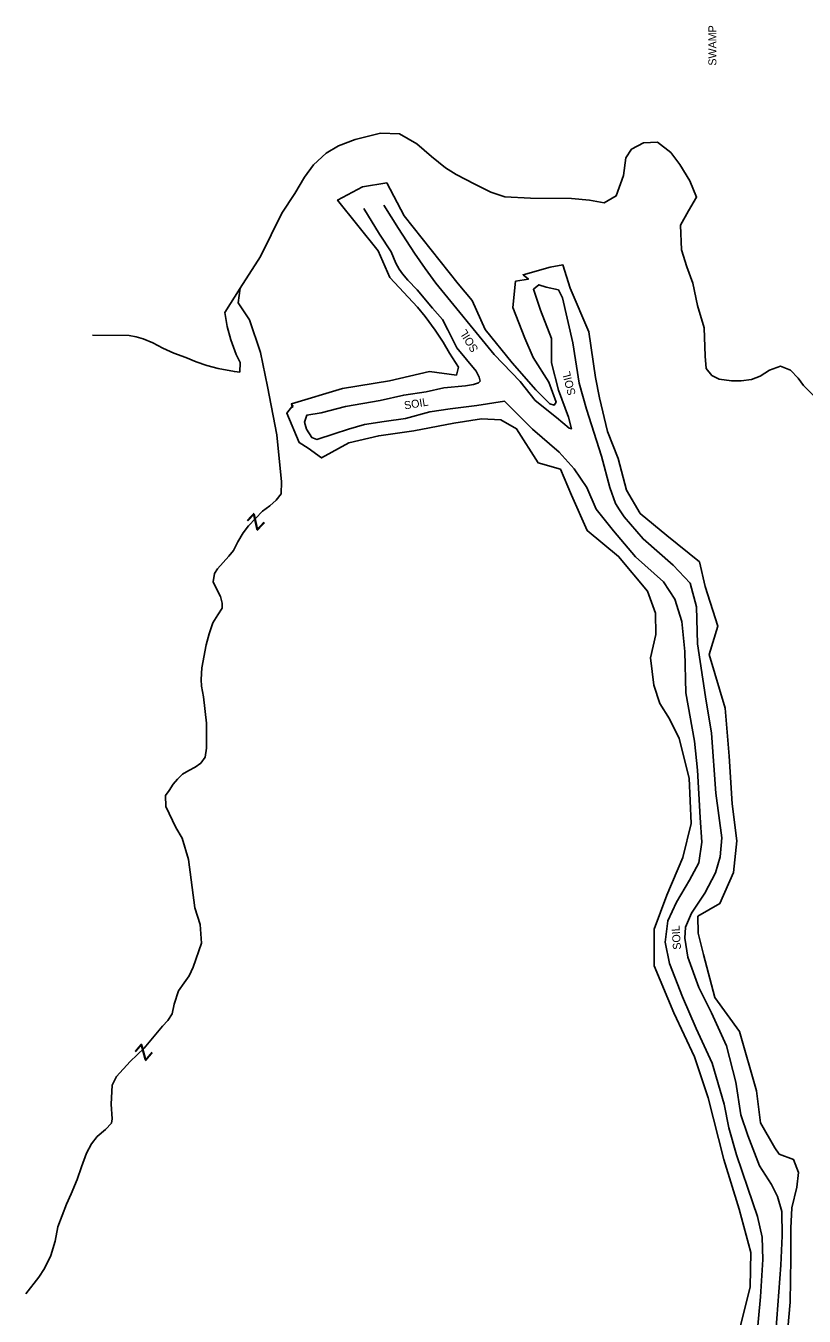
# Model space of a CAD drawing. Extents: x 2030130 to 2036320, y 723205 to 762423.
# Drawn here: x 2031445 to 2031834, y 751056 to 751701 of the extents above; entities that cross this region are included whole.
import ezdxf

# ---------------------------------------------------------------- set-up
doc = ezdxf.new("R2010")
doc.units = 0
for name, color, linetype in [('Draft_Station Labels Major', 7, 'Continuous'), ('Draft_Station Tics Major', 7, 'Continuous'), ('Old_Level_23', 7, 'Continuous'), ('Prop Alignment Horizontal', 7, 'Continuous'), ('Prop Alignment Vertical', 7, 'Continuous')]:
    doc.layers.add(name, color=color, linetype=linetype)

msp = doc.modelspace()

# ---------------------------------------------------------------- linework, layer by layer
at = {"layer": 'Draft_Station Labels Major'}
for points in [[(2031613.92, 751610.21), (2031621.77, 751597.41), (2031627.56, 751588.5), (2031629.94, 751582.79), (2031631.52, 751579.85), (2031633.27, 751577.58), (2031635.91, 751574.36), (2031640.58, 751569.46)], [(2031623.85, 751611.89), (2031631.21, 751600.23), (2031639.15, 751587.81), (2031644.53, 751580.24), (2031649.81, 751572.85)], [(2031810.37, 751046.17), (2031812.15, 751066.06), (2031813.37, 751084.7), (2031813.04, 751095.89), (2031810.7, 751106.18), (2031805.8, 751120.4), (2031800.09, 751137.02), (2031796.26, 751150.48), (2031793.99, 751162.32), (2031788.05, 751182.89), (2031780.02, 751200.16), (2031773.17, 751216), (2031766.6, 751232.7), (2031764.54, 751243.39), (2031765.86, 751254.11), (2031770.09, 751263.33), (2031776.61, 751274.41), (2031781.32, 751283.05), (2031782.74, 751293.39), (2031782.01, 751305.73), (2031780.57, 751329.35), (2031779.13, 751343.9), (2031774.79, 751368.07), (2031774.24, 751388.71), (2031772.8, 751403.74), (2031769.39, 751414.89), (2031763.69, 751423.5), (2031749.74, 751435.97), (2031738.68, 751448.96), (2031729.96, 751459.85), (2031725.29, 751470.6), (2031719, 751479.98), (2031711.57, 751488.28), (2031698.21, 751499.89), (2031684.24, 751513.8), (2031670.28, 751511.7), (2031657.08, 751510), (2031646.87, 751508.52), (2031634.76, 751505.19), (2031623.97, 751503.61), (2031614.15, 751502.23), (2031606.26, 751499.82), (2031598.96, 751497.51), (2031590.31, 751494.71), (2031587.79, 751495.74), (2031585.23, 751499.85), (2031584.22, 751503.31), (2031585.43, 751506.9), (2031592.46, 751508.05), (2031604.68, 751511.19), (2031622.01, 751514.2), (2031633.84, 751516.85), (2031645.01, 751518.53), (2031653.86, 751520.47), (2031664.66, 751521.47), (2031668.61, 751522.1), (2031671.2, 751523), (2031671.96, 751523.88), (2031671.55, 751525.8), (2031669.97, 751528.77), (2031660.37, 751540.52), (2031655.92, 751549.44), (2031653.25, 751554.62), (2031648.26, 751560.35), (2031640.58, 751569.46)], [(2031649.81, 751572.85), (2031679.08, 751537.1), (2031692.07, 751523.75), (2031699.52, 751514.1), (2031710.14, 751505.74), (2031716.48, 751500.32), (2031717.74, 751500.04), (2031716.22, 751505.81), (2031711.23, 751519.26), (2031707.68, 751533.01), (2031707.71, 751539.19), (2031707.73, 751545.17), (2031702.15, 751559.28), (2031698.65, 751569.76), (2031701.42, 751572.01), (2031705, 751570.9), (2031711.1, 751569.52), (2031713.17, 751565.5), (2031718.27, 751542.98), (2031721.51, 751522.86), (2031725.14, 751509.88), (2031732.66, 751486.33), (2031736.91, 751470.76), (2031739.71, 751462.69), (2031741.58, 751459.52), (2031743.94, 751456.08), (2031753.43, 751445), (2031768.45, 751431.87), (2031777.05, 751422.81), (2031780.09, 751411.08), (2031780.61, 751392.47), (2031784.59, 751366.08), (2031787.62, 751347.79), (2031789.82, 751317.9), (2031792.79, 751295.56), (2031792.04, 751286), (2031789.63, 751278.06), (2031784.35, 751267.86), (2031777.62, 751257.94), (2031774.62, 751250.95), (2031774.3, 751245.36), (2031775.86, 751235.92), (2031781.26, 751220.65), (2031787.59, 751208.08), (2031795.22, 751191.49), (2031799.79, 751173.31), (2031802.3, 751157.13), (2031805.8, 751146.66), (2031811.68, 751131.48), (2031817.68, 751122.3), (2031820.65, 751116.25), (2031822.77, 751108.76), (2031822.92, 751096.5), (2031822.23, 751081.93), (2031818.25, 751028.53)]]:
    msp.add_lwpolyline(points, dxfattribs=at)
at = {"layer": 'Draft_Station Tics Major'}
for points in [[(2031660.95, 751572.51), (2031633.97, 751606.5), (2031625.29, 751622.94), (2031613.23, 751621.03), (2031600.71, 751614.37), (2031621.03, 751589.02), (2031626.87, 751575.72), (2031640.68, 751560.79)], [(2031825.28, 751044.6), (2031827.02, 751063.4), (2031827.26, 751085.45), (2031827.34, 751100.35), (2031827.87, 751110.54), (2031830.31, 751120.81), (2031831.14, 751128.17), (2031828.63, 751134.78), (2031821.5, 751137.38), (2031819.24, 751140.53), (2031812.19, 751153.05), (2031810.13, 751169.1), (2031801.63, 751198.74), (2031789.29, 751215.65), (2031783.58, 751237.26), (2031781.02, 751247.86), (2031780.85, 751256.32), (2031791.82, 751262.65), (2031798.65, 751278.17), (2031800.3, 751294.11), (2031797.98, 751312.47), (2031796.56, 751336.36), (2031794.56, 751360.37), (2031786.47, 751387.19), (2031790.78, 751401.41), (2031784.48, 751421.24), (2031781.63, 751433.51), (2031765.38, 751446.64), (2031751.93, 751457.74), (2031745.09, 751469.35), (2031740.99, 751485.17), (2031735.71, 751498.67), (2031731.6, 751515.58), (2031729.7, 751525.66), (2031726.33, 751548.55), (2031716.97, 751570.33), (2031713.35, 751581.94), (2031707.01, 751580.75), (2031693.49, 751577.01), (2031696.12, 751574.86), (2031689.68, 751573.78), (2031688.39, 751560.67), (2031694.36, 751545.38), (2031698.48, 751535.64), (2031706.34, 751523.31), (2031710, 751513.38), (2031708.97, 751511.79), (2031706.86, 751512.48), (2031699.82, 751519.49), (2031688.03, 751533.07), (2031674.43, 751549.71), (2031667.95, 751564.21), (2031660.95, 751572.51)], [(2031640.68, 751560.79), (2031644.55, 751556.11), (2031649.49, 751549.34), (2031653.44, 751543.28), (2031656.72, 751537.81), (2031661.2, 751530.9), (2031660.14, 751526.88), (2031646.74, 751528.66), (2031626.7, 751524.02), (2031603.19, 751520.09), (2031577.68, 751512.46), (2031578.26, 751510.7), (2031578.32, 751511.75), (2031575.33, 751507.76), (2031581.49, 751493.16), (2031585.99, 751490.26), (2031592.63, 751485.47), (2031606.32, 751492.93), (2031621.31, 751496.53), (2031638.87, 751499.05), (2031658.92, 751502.77), (2031672.62, 751504.97), (2031682.28, 751504.5), (2031690.21, 751500.07), (2031701.07, 751482.94), (2031712.13, 751479.78), (2031717.72, 751466.78), (2031725.49, 751449.15), (2031741.16, 751436.21), (2031755.68, 751418.86), (2031759.63, 751407.87), (2031759.76, 751397.24), (2031757.21, 751385.52), (2031758.76, 751371.82), (2031761.89, 751362.73), (2031766.64, 751354.97), (2031771.42, 751345.25), (2031776.4, 751325.41), (2031777.4, 751302.64), (2031773.4, 751285.71), (2031765.29, 751266.84), (2031759, 751249.82), (2031759.03, 751231.56), (2031768.77, 751208.11), (2031779.09, 751186.04), (2031785.9, 751165.57), (2031793.77, 751134.68), (2031801.55, 751109.95), (2031807.27, 751088.29), (2031806.95, 751071.08), (2031800.03, 751042.91)]]:
    msp.add_lwpolyline(points, dxfattribs=at)
at = {"layer": 'Prop Alignment Horizontal'}
for points in [[(2031562.16, 751586.23), (2031572.87, 751607.9), (2031579.31, 751617.68), (2031584.22, 751625.89), (2031588.78, 751631.97), (2031595.08, 751637.88), (2031601.22, 751641.46), (2031609.5, 751644.68), (2031622.24, 751647.78), (2031631.74, 751647.54), (2031640.34, 751642.44), (2031647.61, 751636.16), (2031654.67, 751630.45), (2031659.95, 751627.24), (2031669.32, 751622.35), (2031677.32, 751618.4), (2031684.33, 751615.99), (2031697.13, 751615.41), (2031717.67, 751615.14), (2031726.59, 751614.31), (2031733.98, 751613.06), (2031739.93, 751616.45), (2031743.65, 751626.58), (2031744.87, 751635.51), (2031747.71, 751639.82), (2031753.67, 751643.01), (2031760.64, 751643.31), (2031767.3, 751638.18), (2031771.85, 751632.24), (2031776.82, 751623.99), (2031780.23, 751615.9), (2031776.08, 751609.06), (2031772.12, 751601.83), (2031772.69, 751589.44), (2031775.34, 751580.95), (2031778.37, 751572.86), (2031780.67, 751561.66), (2031783.94, 751550.48)], [(2031562.16, 751586.23), (2031552.03, 751570.28), (2031544.46, 751558.23), (2031545.6, 751551.2), (2031547.42, 751544.47), (2031550.02, 751537.17), (2031552, 751533.24), (2031551.86, 751528.41), (2031549.16, 751528.67), (2031541.13, 751530.11), (2031535.42, 751531.68), (2031530.09, 751533.55), (2031524.96, 751535.61), (2031518.95, 751537.85), (2031513.32, 751540.38), (2031508.46, 751542.93), (2031503.52, 751544.99), (2031500.13, 751546.01), (2031496.55, 751546.64), (2031478.31, 751546.9)], [(2031444.9, 751067.56), (2031451.36, 751075.93), (2031454.29, 751080.31), (2031457.4, 751086.81), (2031459.53, 751093.88), (2031460.89, 751101.13), (2031465.19, 751112.47), (2031467.54, 751117.62), (2031470.54, 751124.7), (2031472.77, 751131.09), (2031475.29, 751137.97), (2031477.65, 751142.63), (2031480.5, 751146.14), (2031484.8, 751149.67), (2031487.65, 751152.88), (2031488.01, 751155.01), (2031487.63, 751162.44), (2031488, 751171.89), (2031490.26, 751176.26), (2031497.12, 751183.68), (2031503.98, 751190.42), (2031513.3, 751201.34), (2031515.87, 751204.27), (2031518.05, 751207.48), (2031519.05, 751212.31), (2031521.29, 751219.09), (2031524.04, 751222.99), (2031526.5, 751226.49), (2031528.57, 751230.95), (2031532.67, 751242.87), (2031532.07, 751252.22), (2031529.37, 751260.58), (2031526.27, 751284.76), (2031523.05, 751295.43), (2031519.9, 751300.7), (2031514.85, 751311.15), (2031514.69, 751316.65), (2031516.49, 751319.28), (2031518.58, 751322.39), (2031520.67, 751324.92), (2031523.24, 751327.37), (2031526.4, 751329.14), (2031529.47, 751330.92), (2031532.34, 751332.79), (2031534.52, 751335.8), (2031535.14, 751340.34), (2031535.18, 751352.89), (2031533.67, 751366.09), (2031532.74, 751371.29), (2031532.5, 751374.76), (2031532.92, 751380.55), (2031534.99, 751391.96), (2031536.57, 751397.57), (2031538.43, 751403), (2031540.89, 751407.08), (2031543.07, 751410.39), (2031543.13, 751412.8), (2031542.22, 751416.26), (2031540.54, 751419.33), (2031538.47, 751423.55), (2031539.19, 751427.61), (2031540.7, 751430.04), (2031546.42, 751436.29), (2031548.79, 751439.11), (2031550.96, 751443.48), (2031553.6, 751448.05), (2031556.26, 751451.55), (2031563.22, 751458.88), (2031566.85, 751461.52), (2031570.1, 751464.27), (2031572.47, 751467.48), (2031572.68, 751473.56), (2031570.37, 751497.07), (2031565.65, 751521.25), (2031562.17, 751538.09), (2031556.66, 751554.42), (2031551.06, 751563.04), (2031552.03, 751570.28)], [(2031783.94, 751550.48), (2031784.5, 751536.3), (2031784.96, 751530.23), (2031787.8, 751526.69), (2031791.49, 751524.81), (2031797.68, 751524.02), (2031802.5, 751524.07), (2031807.7, 751524.62), (2031811.93, 751526.41), (2031816.62, 751529.26), (2031822.09, 751531.26), (2031827.14, 751529.3), (2031831.04, 751525.29), (2031833.59, 751521.75), (2031838.58, 751516.6)]]:
    msp.add_lwpolyline(points, dxfattribs=at)

# ---------------------------------------------------------------- texts
at = {"layer": 'Old_Level_23'}
for rotation, p in [(121.67583, (2031671.26, 751539.83)), (104.75183, (2031719.85, 751517.36)), (9.45752, (2031634.32, 751509.67)), (93.88091, (2031772.43, 751239.74))]:
    msp.add_text('SOIL', height=4, rotation=rotation, dxfattribs=at).set_placement(p)
at = {"layer": 'Prop Alignment Horizontal'}
for rotation, p in [(47.06595, (2031560.37, 751448.54)), (49.84864, (2031504.58, 751183.38))]:
    msp.add_text('z', height=10, rotation=rotation, dxfattribs=at).set_placement(p)
at = {"layer": 'Prop Alignment Vertical'}
msp.add_text('SWAMP', height=4, rotation=90.00002, dxfattribs=at).set_placement((2031790.08, 751681.57))

doc.saveas('drawing.dxf')
